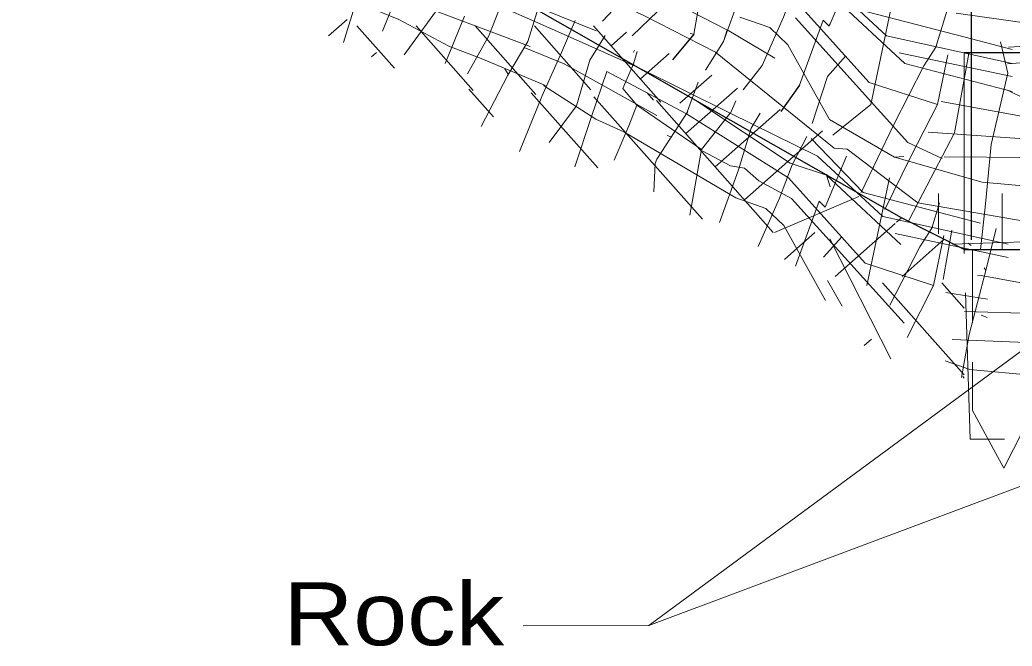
# Model space of a CAD drawing. Extents: x 1083.1 to 1117.1, y 672.5 to 716.5.
# Drawn here: x 1089.081 to 1091.602, y 710.191 to 711.783 of the extents above; entities that cross this region are included whole.
import ezdxf

# ---------------------------------------------------------------- set-up
doc = ezdxf.new("R2010")
doc.units = 0
doc.header["$LTSCALE"] = 0.062
doc.linetypes.add('LONG_DASHED', pattern=[7.5, 6, -1.5])
doc.linetypes.add('MEDIUM_DASHED', pattern=[4.5, 3, -1.5])
doc.layers.add('1', color=7, linetype='Continuous', lineweight=13)

msp = doc.modelspace()

# ---------------------------------------------------------------- linework, layer by layer
at = {"layer": '1', "lineweight": 25}
for p, q in [((1091.32058, 711.27967), (1087.3225, 713.56258)), ((1091.49792, 712.82583), (1091.49792, 711.22383)), ((1090.793, 711.74608), (1090.739, 711.68117)), ((1091.47983, 711.69942), (1094.88667, 711.69942)), ((1091.06158, 711.61658), (1091.01442, 711.54983)), ((1091.47983, 711.19942), (1091.32058, 711.27967)), ((1091.47983, 711.19942), (1094.88667, 711.19942))]:
    msp.add_line(p, q, dxfattribs=at)
at = {"layer": '1'}
for p, q in [((1090.00283, 711.75417), (1090.09292, 711.9805)), ((1090.793, 711.74608), (1090.8225, 711.9125)), ((1091.11717, 711.89583), (1091.28292, 711.742)), ((1091.13725, 711.7665), (1091.19467, 711.904)), ((1089.9395, 711.84133), (1089.90317, 711.72517)), ((1090.61575, 711.83767), (1090.56158, 711.77967)), ((1090.86883, 711.72733), (1090.91667, 711.86058)), ((1091.04383, 711.84033), (1091.23858, 711.62358)), ((1091.14017, 711.84775), (1091.32933, 711.67167)), ((1091.40783, 711.71283), (1091.44958, 711.85033)), ((1090.16, 711.835), (1090.05733, 711.69417)), ((1090.37125, 711.72758), (1090.40233, 711.82575)), ((1090.87717, 711.757), (1090.72342, 711.8365)), ((1090.16167, 711.67217), (1090.21108, 711.79167)), ((1090.41275, 711.80833), (1090.54517, 711.75433)), ((1090.70142, 711.80483), (1090.63633, 711.74242)), ((1090.91025, 711.78983), (1090.9865, 711.76308)), ((1091.23333, 711.80308), (1091.48242, 711.73833)), ((1091.67675, 711.76867), (1091.4595, 711.79983)), ((1089.8655, 711.74183), (1089.91292, 711.78367)), ((1089.93775, 711.76708), (1090.03267, 711.65983)), ((1090.08775, 711.76717), (1090.23275, 711.60308)), ((1090.23783, 711.76725), (1090.39175, 711.59325)), ((1090.38833, 711.76733), (1090.53167, 711.605)), ((1090.45742, 711.69958), (1090.49183, 711.781)), ((1090.53842, 711.76742), (1090.70967, 711.57358)), ((1090.9865, 711.76308), (1091.032, 711.71942)), ((1091.06158, 711.61658), (1091.12167, 711.78167)), ((1090.56767, 711.74308), (1090.52883, 711.68058)), ((1090.58308, 711.71658), (1090.62233, 711.75125)), ((1090.793, 711.74608), (1090.784, 711.74775)), ((1090.86883, 711.72733), (1090.87833, 711.75708)), ((1091.28292, 711.742), (1091.60158, 711.67192)), ((1091.60158, 711.70692), (1091.48242, 711.73833)), ((1090.17133, 711.7155), (1090.25275, 711.68417)), ((1090.32117, 711.64225), (1090.37125, 711.72758)), ((1090.46375, 711.67108), (1090.36208, 711.71275)), ((1090.86883, 711.72733), (1090.823, 711.65492)), ((1091.13808, 711.52925), (1091.032, 711.71942)), ((1091.57233, 711.72708), (1091.59067, 711.64692)), ((1091.65017, 711.71683), (1091.59242, 711.71308)), ((1089.97458, 711.68833), (1089.9875, 711.69975)), ((1090.64017, 711.70092), (1090.64267, 711.70558)), ((1090.64025, 711.67108), (1090.649, 711.70233)), ((1090.65758, 711.63242), (1090.73042, 711.69683)), ((1091.1325, 711.63892), (1091.17958, 711.69108)), ((1091.60158, 711.63842), (1091.31458, 711.69908)), ((1091.41233, 711.5675), (1091.43842, 711.69417)), ((1091.45508, 711.49533), (1091.49142, 711.697)), ((1090.25275, 711.68417), (1090.41683, 711.61575)), ((1090.46375, 711.67108), (1090.69942, 711.53933)), ((1090.52883, 711.68058), (1090.49492, 711.56392)), ((1090.9665, 711.66625), (1090.91875, 711.60458)), ((1091.32933, 711.67167), (1091.60158, 711.60042)), ((1091.59008, 711.67075), (1091.64467, 711.67525)), ((1090.2535, 711.5115), (1090.32117, 711.64225)), ((1090.31342, 711.65833), (1090.322, 711.64458)), ((1090.53242, 711.53483), (1090.57242, 711.65133)), ((1090.65358, 711.66075), (1090.88592, 711.54517)), ((1090.758, 711.57058), (1090.83892, 711.64217)), ((1091.1325, 711.63892), (1091.09375, 711.51925)), ((1091.54833, 711.46617), (1091.59067, 711.64692)), ((1090.77458, 711.54358), (1090.80417, 711.62475)), ((1091.23858, 711.62358), (1091.41233, 711.5675)), ((1090.22183, 711.60692), (1090.28408, 711.5365)), ((1090.3805, 711.59717), (1090.54942, 711.40633)), ((1090.53967, 711.58742), (1090.81517, 711.276)), ((1090.67475, 711.59725), (1090.691, 711.57892)), ((1090.77292, 711.4935), (1090.90392, 711.60942)), ((1090.83383, 711.58742), (1090.83492, 711.58617)), ((1091.63517, 711.58175), (1091.59008, 711.604)), ((1090.49492, 711.56392), (1090.42558, 711.47133)), ((1090.64825, 711.566), (1090.8125, 711.45317)), ((1090.69842, 711.57775), (1090.99492, 711.24258)), ((1090.90025, 711.57667), (1090.886, 711.54517)), ((1091.4215, 711.57508), (1091.68733, 711.52608)), ((1090.8125, 711.45317), (1090.88592, 711.54517)), ((1090.84742, 711.40933), (1091.01225, 711.55492)), ((1090.88592, 711.54517), (1091.10717, 711.4365)), ((1090.96183, 711.54592), (1090.93908, 711.50775)), ((1090.53242, 711.53483), (1090.49108, 711.40958)), ((1090.61508, 711.49775), (1090.90025, 711.3305)), ((1090.72592, 711.48908), (1090.735, 711.48558)), ((1090.90667, 711.40125), (1090.93908, 711.50775)), ((1090.92192, 711.32508), (1091.12033, 711.50042)), ((1091.04317, 711.41408), (1091.08033, 711.48667)), ((1091.64467, 711.47933), (1091.38833, 711.49717)), ((1092.33517, 711.46533), (1090.67883, 710.24383)), ((1091.09142, 711.48108), (1091.22333, 711.34375)), ((1090.783, 711.28675), (1090.8125, 711.45317)), ((1091.10717, 711.4365), (1091.27292, 711.28267)), ((1091.12725, 711.30717), (1091.18117, 711.43625)), ((1091.64467, 711.43258), (1091.42867, 711.43483)), ((1090.85883, 711.268), (1090.90667, 711.40125)), ((1090.92225, 711.40567), (1090.95833, 711.3735)), ((1091.13017, 711.38842), (1091.1395, 711.35867)), ((1091.13017, 711.38842), (1091.31933, 711.21233)), ((1090.95833, 711.3735), (1091.04133, 711.3285)), ((1091.03383, 711.381), (1091.22858, 711.16425)), ((1091.29017, 711.38167), (1091.2325, 711.10783)), ((1090.99833, 711.24258), (1091.21242, 711.33417)), ((1091.22333, 711.34375), (1091.47242, 711.279)), ((1091.41475, 711.34133), (1091.41475, 711.23883)), ((1091.5765, 711.34133), (1091.5765, 711.19942)), ((1090.90025, 711.3305), (1090.9765, 711.30375)), ((1091.04133, 711.3285), (1091.32717, 711.01192)), ((1091.05158, 711.15725), (1091.11167, 711.32233)), ((1091.39783, 711.2535), (1091.41742, 711.318)), ((1090.9765, 711.30375), (1091.022, 711.26008)), ((1091.53283, 711.30667), (1091.52117, 711.19942)), ((1091.12808, 711.06992), (1091.022, 711.26008)), ((1091.152, 711.13075), (1091.30433, 711.26558)), ((1091.27292, 711.28267), (1091.59158, 711.21258)), ((1091.30775, 711.26833), (1091.32058, 711.27967)), ((1091.52108, 711.26617), (1091.47242, 711.279)), ((1091.02333, 711.17392), (1091.10092, 711.24258)), ((1091.59158, 711.17908), (1091.30458, 711.23975)), ((1091.40233, 711.10817), (1091.42842, 711.23483)), ((1091.42633, 711.12325), (1091.44883, 711.24808)), ((1091.1225, 711.17958), (1091.16958, 711.23175)), ((1091.139, 711.22642), (1091.29375, 710.92158)), ((1091.32217, 711.13075), (1091.42883, 711.22508)), ((1091.4495, 711.213), (1091.65842, 711.21967)), ((1091.48975, 711.21533), (1091.4975, 711.2095)), ((1091.36742, 711.20617), (1091.29133, 711.0575)), ((1091.22858, 711.16425), (1091.40233, 711.10817)), ((1091.4925, 710.98308), (1091.53467, 711.14617)), ((1091.52325, 711.133), (1091.51375, 711.13242)), ((1091.62483, 711.11475), (1091.52325, 711.133)), ((1091.13275, 711.12025), (1091.16967, 711.05517)), ((1091.27283, 711.11467), (1091.47983, 710.88067)), ((1091.40233, 711.10817), (1091.33483, 710.97592)), ((1091.42308, 711.11475), (1091.47983, 711.05058)), ((1091.43342, 711.08975), (1091.53875, 711.07325)), ((1091.65867, 711.037), (1091.48042, 711.04158)), ((1091.53867, 711.02633), (1091.52317, 711.03267)), ((1091.4925, 710.98308), (1091.47283, 710.87392)), ((1091.22583, 710.95492), (1091.24467, 710.97158)), ((1091.66242, 710.96167), (1091.4495, 710.97033)), ((1091.43175, 710.9165), (1091.49458, 710.89467)), ((1091.66658, 710.87783), (1091.49458, 710.89467)), ((1092.34275, 710.86775), (1090.67883, 710.24383)), ((1091.47617, 710.87625), (1091.47983, 710.87208)), ((1090.67883, 710.24383), (1090.3595, 710.24342))]:
    msp.add_line(p, q, dxfattribs=at)
at = {"layer": '1', "linetype": 'LONG_DASHED'}
msp.add_line((1091.47983, 711.19942), (1091.47983, 711.57625), dxfattribs=at)
at = {"layer": '1', "linetype": 'MEDIUM_DASHED'}
for p, q in [((1091.50075, 711.19875), (1091.50075, 710.79033)), ((1091.50075, 710.79033), (1091.58092, 710.64333)), ((1091.58092, 710.64333), (1091.65475, 710.79033))]:
    msp.add_line(p, q, dxfattribs=at)
at = {"layer": '1'}
for points in [[(1090.9665, 711.66625), (1091.02067, 711.78917), (1091.05317, 711.87342), (1091.1225, 712.00875), (1091.11492, 712.10583), (1091.1625, 712.16817), (1091.18967, 712.23875)], [(1091.40367, 712.09742), (1091.32183, 711.94383), (1091.2425, 711.56717), (1091.146, 711.4895)], [(1089.6655, 712.00167), (1090.05317, 711.83783), (1090.37775, 711.71483)], [(1090.07892, 711.91575), (1090.43975, 711.75608), (1090.65358, 711.66075)], [(1089.77317, 711.89483), (1090.04392, 711.78392), (1090.17133, 711.7155)], [(1090.50108, 711.86892), (1090.66658, 711.79375), (1090.84825, 711.70017), (1091.14942, 711.45642), (1091.18275, 711.454)], [(1090.21842, 711.64525), (1090.27292, 711.74183), (1090.30625, 711.82842)], [(1091.05133, 711.78783), (1091.33717, 711.47125), (1091.42417, 711.43042)], [(1091.12167, 711.78167), (1091.13725, 711.7665), (1091.139, 711.77267)], [(1090.87833, 711.75708), (1090.99917, 711.685), (1090.995, 711.68783)], [(1091.37742, 711.6655), (1091.40783, 711.71283), (1091.40975, 711.71708)], [(1090.35025, 711.44808), (1090.40758, 711.58808), (1090.45742, 711.69958)], [(1090.59092, 711.426), (1090.62808, 711.51367), (1090.64825, 711.566), (1090.61267, 711.6085), (1090.64025, 711.67108)], [(1091.37742, 711.6655), (1091.30133, 711.51683), (1091.21842, 711.34367)], [(1091.03383, 711.381), (1090.77458, 711.54358), (1090.57242, 711.65133)], [(1091.038, 711.41867), (1090.80367, 711.57417), (1090.65358, 711.66075)], [(1090.61508, 711.49775), (1090.5445, 711.53017), (1090.41117, 711.6155)], [(1091.41233, 711.5675), (1091.34483, 711.43525), (1091.27833, 711.30092)], [(1090.69925, 711.42875), (1090.77833, 711.54983), (1090.77592, 711.55075)], [(1091.13808, 711.52925), (1091.30283, 711.4335), (1091.32692, 711.43525)], [(1091.45508, 711.49533), (1091.37483, 711.34133), (1091.33933, 711.27325)], [(1091.54833, 711.46617), (1091.53625, 711.34133), (1091.53283, 711.30667)], [(1090.81458, 711.44975), (1090.88642, 711.41158), (1090.92225, 711.40567)], [(1091.18275, 711.454), (1091.33125, 711.34133), (1091.3625, 711.31767)], [(1090.69142, 711.3455), (1090.69483, 711.41742), (1090.69925, 711.42875)], [(1090.9565, 711.20692), (1091.01067, 711.32983), (1091.04317, 711.41408)], [(1091.038, 711.41867), (1091.13017, 711.38842), (1091.132, 711.39)], [(1091.30283, 711.4335), (1091.52583, 711.37017), (1091.81758, 711.34392)], [(1091.11167, 711.32233), (1091.12725, 711.30717), (1091.129, 711.31333)], [(1091.3625, 711.31767), (1091.65658, 711.26733), (1092.02067, 711.25858), (1092.36375, 711.23667), (1092.56442, 711.26508)], [(1091.36742, 711.20617), (1091.39783, 711.2535), (1091.39975, 711.25775)], [(1091.56117, 711.25267), (1091.53467, 711.14617), (1091.53067, 711.15275)]]:
    msp.add_lwpolyline(points, dxfattribs=at)
msp.add_lwpolyline([(1091.47983, 711.19942), (1091.47983, 711.69942), (1094.88667, 711.69942), (1094.88667, 711.19942)], close=True, dxfattribs=at)
at = {"layer": '1', "linetype": 'LONG_DASHED'}
msp.add_lwpolyline([(1091.47983, 711.19942), (1094.88667, 711.19942), (1094.88667, 710.71767), (1091.49483, 710.71767)], close=True, dxfattribs=at)

# ---------------------------------------------------------------- texts
at = {"layer": '1', "width": 1.15}
msp.add_text('Rock', height=0.16, dxfattribs=at).set_placement((1089.75075, 710.19375))

doc.saveas('drawing.dxf')
